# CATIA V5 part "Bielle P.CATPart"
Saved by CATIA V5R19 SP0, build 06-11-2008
Part number: Bielle P
Bounding box of the stored display mesh (mm): x -140 to 140, y 200 to 304.01, z -1349.993 to -50
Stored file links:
  G:\EU_thinkMotion\CFAO_2010\MMS_groupe3\MMS_groupe3\rdalborgo\rdalborgo\Bielle P.CATPart
  G:\EU_thinkMotion\CFAO_2010\MMS_groupe3\MMS_groupe3\rdalborgo\rdalborgo\rdalborgo.CATProduct
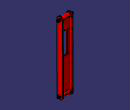
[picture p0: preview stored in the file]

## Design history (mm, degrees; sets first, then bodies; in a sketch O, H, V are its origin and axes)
External parameters (linked from other documents)
  `External.Largeur bielle` = 210 mm
  `External.Longueur Bielle` = 1200 mm
Set1
  Plane1: linked copy from another document
  Point1 "B bielle": linked copy from another document
  Point2 "C bielle": linked copy from another document
Body1 (main body)
  Sketch1 on Plane1, origin (0, 0, 0), H (0, 1, 0), V (0, 0, 1)
    circle A1 centre (250, -100) radius 15
    point P1 (250, -100)
    arc A2 centre (250, -100) radius 50 from (299.9997, -99.8329) to (200, -100) ccw
    point P2 (250, -100)
    reference projected point E1 (250, -100) from Point1
    circle A3 centre (254.0096, -1299.9933) radius 15
    point P3 (254.0096, -1299.9933)
    point P4 (254.0096, -1299.9933)
    reference projected point E2 (254.0096, -1299.9933) from Point2
    line L1 (200, -100) -> (204.0096, -1299.9933)
    point P5 (200, -100)
    line L2 (304.0096, -1299.9933) -> (299.9997, -99.8329)
    point P7 (304.0096, -1299.9933)
    point P8 (299.9997, -99.8329)
    point P9 (299.9997, -99.8329)
    arc A4 centre (254.0096, -1299.9933) radius 50 from (204.0096, -1299.9933) to (304.0096, -1299.9933) ccw
    point P10 (304.0096, -1299.9933)
    radius A1 = 15
    radius A2 = 50
    radius A3 = 15
    radius A4 = 50
    coincidence: P2 P1, P1 E1, P4 P3, P3 E2, P5 A2, P8 A2, P7 P10, P8 P9
    tangency: L2 A2
  Pad1: profile Sketch1, direction (1, 0, 0), length 95 {= `External.Largeur bielle` /2-10mm}, mirrored extent
  Sketch2 on Plane1, origin (0, 0, 0), H (0, 1, 0), V (0, 0, 1)
    arc A1 centre (250, -100) radius 35 from (285, -100) to (240, -133.541) ccw
    point P1 (250, -100)
    reference projected point E1 (250, -100) from Point1
    arc A2 centre (254.0096, -1299.9933) radius 35 from (289.0096, -1299.9933) to (260, -1265.5098) ccw
    point P2 (254.0096, -1299.9933)
    reference projected point E2 (254.0096, -1299.9933) from Point2
    line L1 (240, -1267.9194) -> (240, -133.541)
    point P3 (240, -1267.9194)
    line L2 (260, -133.541) -> (260, -1265.5098)
    point P5 (260, -133.541)
    point P6 (260, -1265.5098)
    reference projected point E3 (250, -100) from Point1
    arc A3 centre (250, -100) radius 35 from (260, -133.541) to (285, -100) ccw
    point P7 (285, -100)
    point P8 (285, -100)
    point P9 (289.0096, -1299.9933)
    point P10 (289.0096, -1299.9933)
    arc A4 centre (254.0096, -1299.9933) radius 35 from (240, -1267.9194) to (289.0096, -1299.9933) ccw
    radius A1 = 35
    radius A2 = 35
    distance L1 L2 = 20
    distance L1 E3 = 10
    coincidence: P1 E1, P2 E2, P3 A2, P5 A1, P6 A2, A1 A3, P7 P8, P9 P10
    vertical: L1 V, L2 V
  Pocket1: profile Sketch2, direction (-1, 0, 0), length 75 {= `External.Largeur bielle` /2-30mm}, mirrored extent, outer side
  Sketch3 on face of Pocket1 from Sketch2.L2, origin (0, 260, 0), H (-1, 0, 0), V (0, 0, 1)
    line L1 (-60, -300) -> (60, -300)
    line L2 (60, -300) -> (60, -700)
    line L3 (60, -700) -> (-60, -700)
    line L4 (-60, -700) -> (-60, -300)
    reference projected point E1 (0, -100) from Point1
    reference projected point E2 (0, -100) from Point1
    distance L4 L2 = 120 {= `External.Largeur bielle` -90mm}
    distance L2 E1 = 60 {= (`External.Largeur bielle` -90mm)/2}
    distance L3 L1 = 400 {= `External.Longueur Bielle` /2-200mm}
    distance L1 E2 = 200
    horizontal: L1 H, L3 H
    vertical: L2 V, L4 V
  Pocket2: profile Sketch3, direction (0, 1, 0), length 75, mirrored extent
  Sketch4 on Plane1, origin (0, 0, 0), H (0, 1, 0), V (0, 0, 1)
    circle A1 centre (250, -100) radius 15
    point P1 (250, -100)
    circle A2 centre (250, -100) radius 25
    point P2 (250, -100)
    point P3 (254.0096, -1299.9933)
    point P4 (254.0096, -1299.9933)
    circle A3 centre (254.0096, -1299.9933) radius 15
    circle A4 centre (254.0096, -1299.9933) radius 25
    reference projected point E1 (250, -100) from Point1
    reference projected point E2 (254.0096, -1299.9933) from Point2
    radius A1 = 15
    radius A2 = 25
    radius A3 = 15
    radius A4 = 25
    coincidence: P2 P1, P4 P3, P2 E1, P4 E2
  Pad2: profile Sketch4, direction (1, 0, 0), length 105 {= `External.Largeur bielle` /2}, mirrored extent
Body2 "Axe Bielle 1"
  Sketch5 on Plane1, origin (0, 0, 0), H (0, 1, 0), V (0, 0, 1)
    circle A1 centre (250, -100) radius 15
    point P1 (250, -100)
    reference projected point E1 (250, -100) from Point1
    radius A1 = 15
    coincidence: P1 E1
  Pad3: profile Sketch5, direction (1, 0, 0), length 125 {= `External.Largeur bielle` /2+20mm}, mirrored extent
  Sketch6 on start face of Pad3, origin (-125, 0, 0), H (0, -1, 0), V (0, 0, 1)
    circle A1 centre (-250, -100) radius 20
    point P1 (-250, -100)
    reference projected point E1 (-250, -100) from Point1
    radius A1 = 20
    coincidence: P1 E1
  Pad4: profile Sketch6, direction (-1, 0, 0), length 5
  Sketch7 on end face of Pad4, origin (-130, 0, 0), H (0, -1, 0), V (0, 0, 1)
    point P1 (-250, -100)
    point P2 (-258.6603, -115)
    point P3 (-241.3397, -115)
    point P4 (-232.6795, -100)
    point P5 (-241.3397, -85)
    point P6 (-258.6603, -85)
    point P7 (-267.3205, -100)
    point P8 (-250, -115)
    line L1 (-258.6603, -115) -> (-241.3397, -115)
    line L2 (-241.3397, -115) -> (-232.6795, -100)
    line L3 (-232.6795, -100) -> (-241.3397, -85)
    line L4 (-241.3397, -85) -> (-258.6603, -85)
    line L5 (-258.6603, -85) -> (-267.3205, -100)
    line L6 (-267.3205, -100) -> (-258.6603, -115)
    construction line L7 (-250, -100) -> (-250, -115)
    construction circle A1 centre (-250, -100) radius 17.3205
    construction arc A2 centre (-258.6603, -85) radius 17.3205 from (-241.3397, -85) to (-267.3205, -100) cw
    construction arc A3 centre (-241.3397, -115) radius 17.3205 from (-232.6795, -100) to (-258.6603, -115) ccw
    reference projected point E1 (-250, -100) from Point1
    distance L1 L4 = 30
    vertical: L7 V
    coincidence: A1 P2, A1 P3, A1 P4, A1 P5, A1 P6, A1 P7, A2 P1, A3 P1, P1 E1
    midpoint: P8 L1
  Pad5: profile Sketch7, direction (-1, 0, 0), length 10
  Sketch8 on end face of Pad3, origin (125, 0, 0), H (0, 1, 0), V (0, 0, 1)
    circle A1 centre (250, -100) radius 10
    point P1 (250, -100)
    reference projected point E1 (250, -100) from Point1
    radius A1 = 10
    coincidence: P1 E1
  Pad6: profile Sketch8, direction (1, 0, 0), length 15
  Sketch9 on end face of Pad3, origin (125, 0, 0), H (0, 1, 0), V (0, 0, 1)
    circle A1 centre (250, -100) radius 10
    point P1 (250, -100)
    circle A2 centre (250, -100) radius 20
    point P2 (250, -100)
    reference projected point E1 (250, -100) from Point1
    radius A1 = 10
    radius A2 = 20
    coincidence: P2 P1, P2 E1
  Pad7: profile Sketch9, direction (1, 0, 0), length 5
  Sketch10 on end face of Pad7, origin (130, 0, 0), H (0, 1, 0), V (0, 0, 1)
    point P1 (250, -100)
    point P2 (255.3622, -116.4696)
    point P3 (266.9442, -103.591)
    point P4 (261.582, -87.1214)
    point P5 (244.6378, -83.5304)
    point P6 (233.0558, -96.409)
    point P7 (238.418, -112.8786)
    point P8 (261.1532, -110.0303)
    line L1 (255.3622, -116.4696) -> (266.9442, -103.591)
    line L2 (266.9442, -103.591) -> (261.582, -87.1214)
    line L3 (261.582, -87.1214) -> (244.6378, -83.5304)
    line L4 (244.6378, -83.5304) -> (233.0558, -96.409)
    line L5 (233.0558, -96.409) -> (238.418, -112.8786)
    line L6 (238.418, -112.8786) -> (255.3622, -116.4696)
    construction line L7 (250, -100) -> (261.1532, -110.0303)
    construction circle A1 centre (250, -100) radius 17.3205
    construction arc A2 centre (233.0558, -96.409) radius 17.3205 from (244.6378, -83.5304) to (238.418, -112.8786) cw
    construction arc A3 centre (266.9442, -103.591) radius 17.3205 from (261.582, -87.1214) to (255.3622, -116.4696) ccw
    reference projected point E1 (250, -100) from Point1
    circle A4 centre (250, -100) radius 10
    point P9 (250, -100)
    reference projected point E2 (250, -100) from Point1
    distance L3 L6 = 30
    radius A4 = 10
    coincidence: A1 P2, A1 P3, A1 P4, A1 P5, A1 P6, A1 P7, A2 P1, A3 P1, P1 E1, P9 E2
    midpoint: P8 L1
    parallelism: L1 L4
  Pad8: profile Sketch10, direction (1, 0, 0), length 8
Body3 "Axe Bielle 2"
  Sketch11 on Plane1, origin (0, 0, 0), H (0, 1, 0), V (0, 0, 1)
    circle A1 centre (254.0096, -1299.9933) radius 15
    point P1 (254.0096, -1299.9933)
    reference projected point E1 (254.0096, -1299.9933) from Point2
    radius A1 = 15
    coincidence: P1 E1
  Pad9: profile Sketch11, direction (1, 0, 0), length 120 {= `External.Largeur bielle` /2+15mm}, mirrored extent
  Sketch12 on start face of Pad9, origin (-120, 0, 0), H (0, -1, 0), V (0, 0, 1)
    circle A1 centre (-254.0096, -1299.9933) radius 20
    point P1 (-254.0096, -1299.9933)
    reference projected point E1 (-254.0096, -1299.9933) from Point2
    radius A1 = 20
    coincidence: P1 E1
  Pad10: profile Sketch12, direction (-1, 0, 0), length 5
  Sketch13 on end face of Pad10, origin (-125, 0, 0), H (0, -1, 0), V (0, 0, 1)
    point P1 (-254.0096, -1299.9933)
    point P2 (-262.6698, -1314.9933)
    point P3 (-245.3493, -1314.9933)
    point P4 (-236.6891, -1299.9933)
    point P5 (-245.3493, -1284.9933)
    point P6 (-262.6698, -1284.9933)
    point P7 (-271.3301, -1299.9933)
    point P8 (-254.0096, -1314.9933)
    line L1 (-262.6698, -1314.9933) -> (-245.3493, -1314.9933)
    line L2 (-245.3493, -1314.9933) -> (-236.6891, -1299.9933)
    line L3 (-236.6891, -1299.9933) -> (-245.3493, -1284.9933)
    line L4 (-245.3493, -1284.9933) -> (-262.6698, -1284.9933)
    line L5 (-262.6698, -1284.9933) -> (-271.3301, -1299.9933)
    line L6 (-271.3301, -1299.9933) -> (-262.6698, -1314.9933)
    construction line L7 (-254.0096, -1299.9933) -> (-254.0096, -1314.9933)
    construction circle A1 centre (-254.0096, -1299.9933) radius 17.3205
    construction arc A2 centre (-262.6698, -1284.9933) radius 17.3205 from (-245.3493, -1284.9933) to (-271.3301, -1299.9933) cw
    construction arc A3 centre (-245.3493, -1314.9933) radius 17.3205 from (-236.6891, -1299.9933) to (-262.6698, -1314.9933) ccw
    reference projected point E1 (-254.0096, -1299.9933) from Point2
    distance L1 L4 = 30
    vertical: L7 V
    coincidence: A1 P2, A1 P3, A1 P4, A1 P5, A1 P6, A1 P7, A2 P1, A3 P1, P1 E1
    midpoint: P8 L1
  Pad11: profile Sketch13, direction (-1, 0, 0), length 10
  Sketch14 on end face of Pad9, origin (120, 0, 0), H (0, 1, 0), V (0, 0, 1)
    circle A1 centre (254.0096, -1299.9933) radius 10
    point P1 (254.0096, -1299.9933)
    reference projected point E1 (254.0096, -1299.9933) from Point2
    radius A1 = 10
    coincidence: P1 E1
  Pad12: profile Sketch14, direction (1, 0, 0), length 15
  Sketch15 on end face of Pad9, origin (120, 0, 0), H (0, 1, 0), V (0, 0, 1)
    circle A1 centre (254.0096, -1299.9933) radius 10
    point P1 (254.0096, -1299.9933)
    circle A2 centre (254.0096, -1299.9933) radius 20
    point P2 (254.0096, -1299.9933)
    reference projected point E1 (254.0096, -1299.9933) from Point2
    radius A1 = 10
    radius A2 = 20
    coincidence: P2 P1, P2 E1
  Pad13: profile Sketch15, direction (1, 0, 0), length 5
  Sketch16 on end face of Pad13, origin (125, 0, 0), H (0, 1, 0), V (0, 0, 1)
    point P1 (254.0096, -1299.9933)
    point P2 (259.3717, -1316.4629)
    point P3 (270.9537, -1303.5843)
    point P4 (265.5915, -1287.1147)
    point P5 (248.6474, -1283.5237)
    point P6 (237.0654, -1296.4023)
    point P7 (242.4276, -1312.8719)
    point P8 (265.1627, -1310.0236)
    line L1 (259.3717, -1316.4629) -> (270.9537, -1303.5843)
    line L2 (270.9537, -1303.5843) -> (265.5915, -1287.1147)
    line L3 (265.5915, -1287.1147) -> (248.6474, -1283.5237)
    line L4 (248.6474, -1283.5237) -> (237.0654, -1296.4023)
    line L5 (237.0654, -1296.4023) -> (242.4276, -1312.8719)
    line L6 (242.4276, -1312.8719) -> (259.3717, -1316.4629)
    construction line L7 (254.0096, -1299.9933) -> (265.1627, -1310.0236)
    construction circle A1 centre (254.0096, -1299.9933) radius 17.3205
    construction arc A2 centre (237.0654, -1296.4023) radius 17.3205 from (248.6474, -1283.5237) to (242.4276, -1312.8719) cw
    construction arc A3 centre (270.9537, -1303.5843) radius 17.3205 from (265.5915, -1287.1147) to (259.3717, -1316.4629) ccw
    reference projected point E1 (254.0096, -1299.9933) from Point2
    circle A4 centre (254.0096, -1299.9933) radius 10
    point P9 (254.0096, -1299.9933)
    reference projected point E2 (254.0096, -1299.9933) from Point2
    distance L3 L6 = 30
    radius A4 = 10
    coincidence: A1 P2, A1 P3, A1 P4, A1 P5, A1 P6, A1 P7, A2 P1, A3 P1, P1 E1, P9 E2
    midpoint: P8 L1
    parallelism: L1 L4
  Pad14: profile Sketch16, direction (1, 0, 0), length 8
